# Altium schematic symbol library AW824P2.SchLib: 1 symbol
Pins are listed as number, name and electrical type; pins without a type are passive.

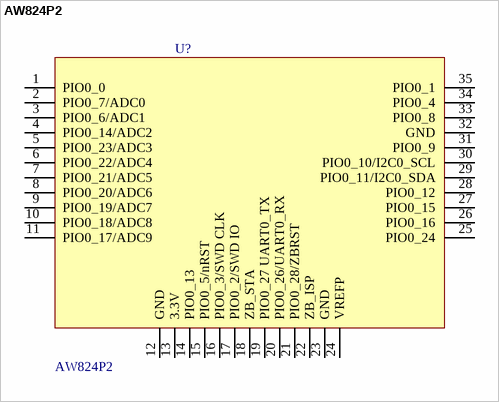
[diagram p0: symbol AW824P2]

## AW824P2
designator U?
footprint AW824P2EF
pins: 1 PIO0_0, 2 PIO0_7/ADC0, 3 PIO0_6/ADC1, 4 PIO0_14/ADC2, 5 PIO0_23/ADC3, 6 PIO0_22/ADC4, 7 PIO0_21/ADC5, 8 PIO0_20/ADC6, 9 PIO0_19/ADC7, 10 PIO0_18/ADC8, 11 PIO0_17/ADC9, 12 GND, 13 3.3V, 14 PIO0_13, 15 PIO0_5/nRST, 16 PIO0_3/SWD CLK, 17 PIO0_2/SWD IO, 18 ZB_STA, 19 PIO0_27 UART0_TX, 20 PIO0_26/UART0_RX, 21 PIO0_28/ZBRST, 22 ZB_ISP, 23 GND, 24 VREFP, 25 PIO0_24, 26 PIO0_16, 27 PIO0_15, 28 PIO0_12, 29 PIO0_11/I2C0_SDA, 30 PIO0_10/I2C0_SCL, 31 PIO0_9, 32 GND, 33 PIO0_8, 34 PIO0_4, 35 PIO0_1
